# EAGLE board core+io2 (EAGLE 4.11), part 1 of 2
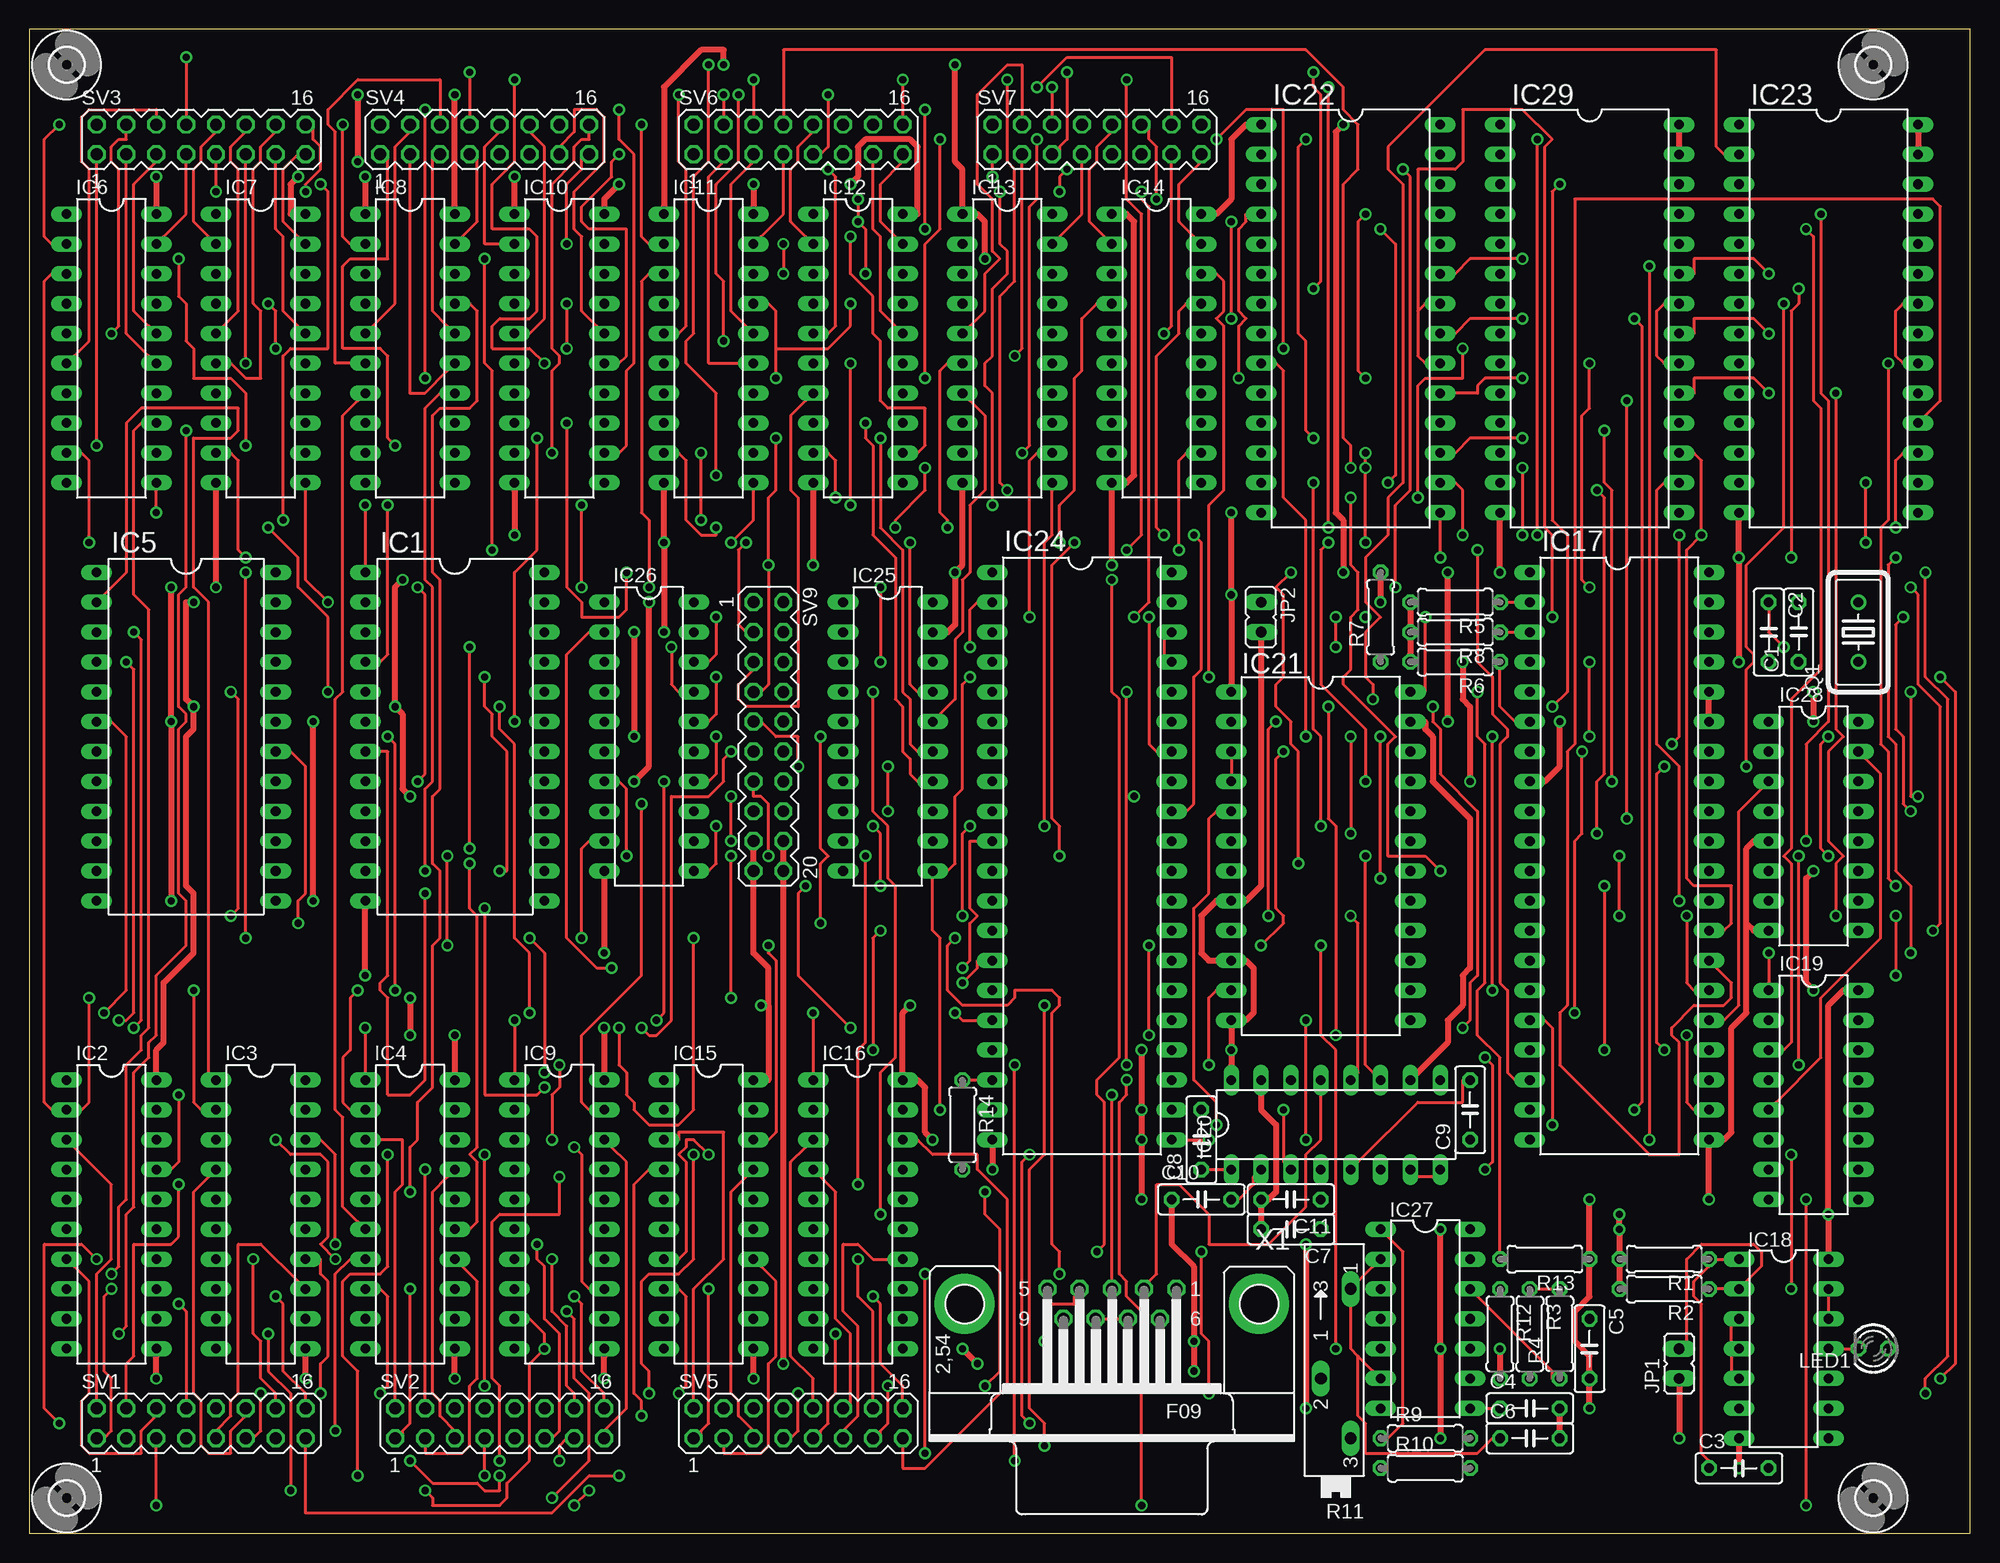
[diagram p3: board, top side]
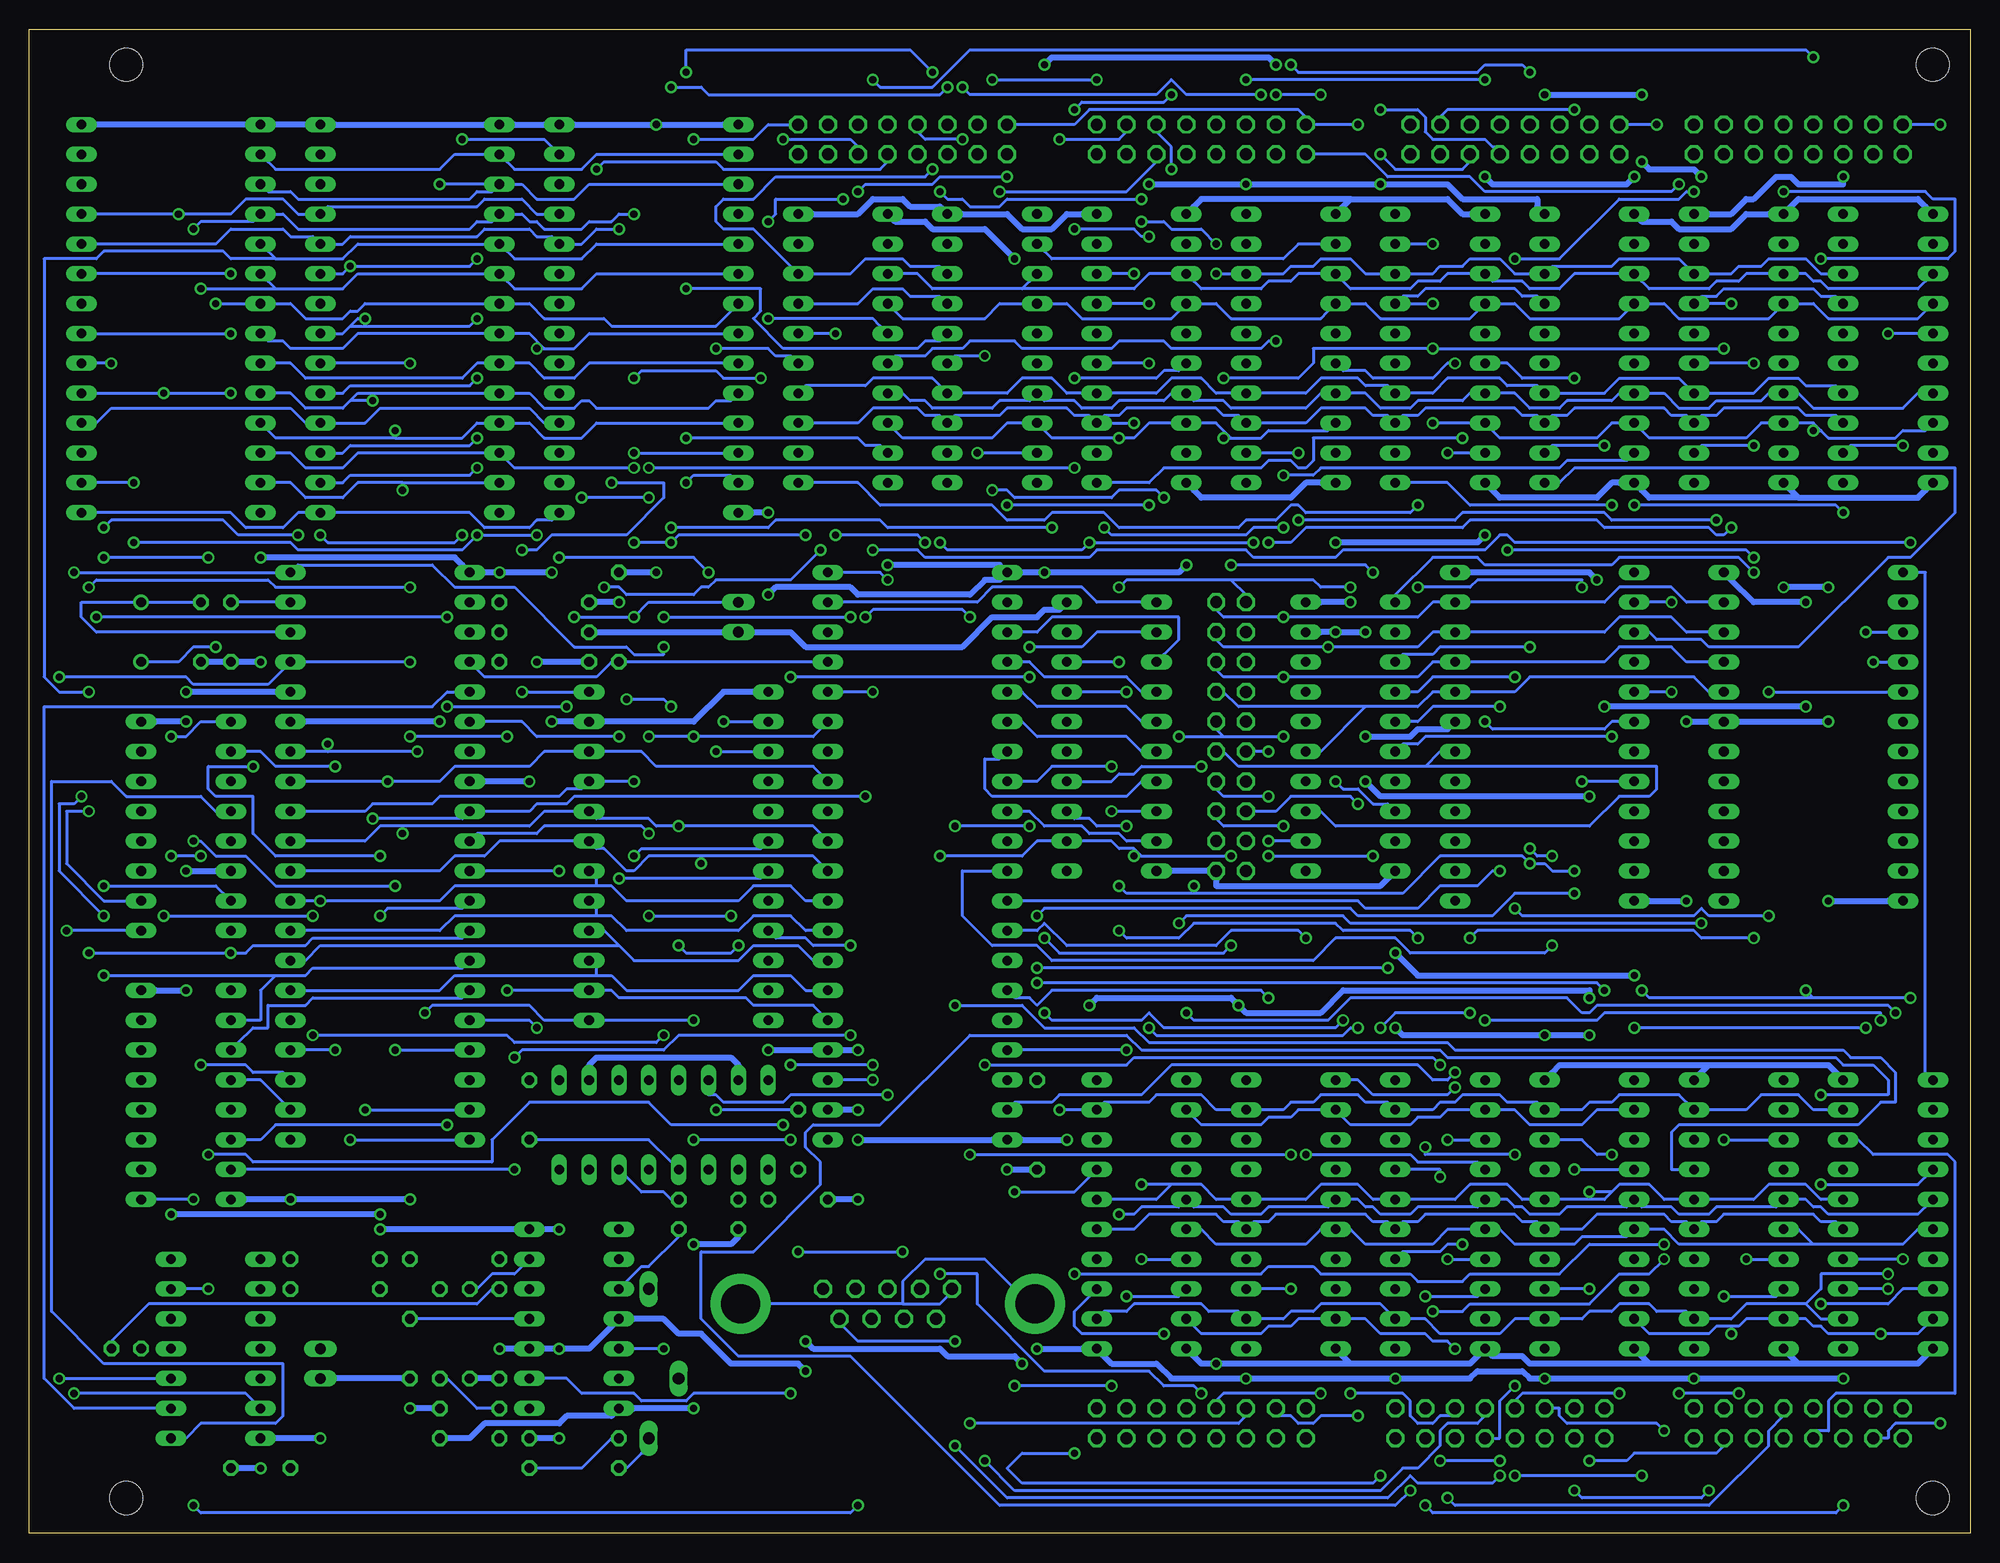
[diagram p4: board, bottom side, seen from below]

Size 165.08 x 127.94 mm. Coordinates in mm from the lower left corner, seen from the top.
Outline: 0,0 165.08,0 165.08,127.94 0,127.94 0,0
Copper layers (1*16): Top 0.035mm / dielectric 1.5mm / Bottom 0.035mm
Design rules "default": minimum track width 10mil, minimum drill 24mil, track to track 8mil, track to pad 8mil, pad to pad 8mil, via to via 8mil, smd to smd 8mil, copper to edge 40mil, drill to drill 8mil, minimum pad ring 10mil, minimum via ring 8mil, stop-mask expansion 4mil, vias tented up to drill 0mil, thermal gap 10mil
Net classes: 1 Power: width 0.508 mm, drill 0.254 mm, clearance 0.254 mm

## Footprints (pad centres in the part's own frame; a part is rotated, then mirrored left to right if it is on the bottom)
C050-025X075 = drill 0.813 octagon: 1 -2.54,0; 2 2.54,0
DIL24-6 = drill 0.813 long: 1 -13.97,-7.62; 2 -11.43,-7.62; 3 -8.89,-7.62; 4 -6.35,-7.62; 5 -3.81,-7.62; 6 -1.27,-7.62; 7 1.27,-7.62; 8 3.81,-7.62; 9 6.35,-7.62; 10 8.89,-7.62; 11 11.43,-7.62; 12 13.97,-7.62; 13 13.97,7.62; 14 11.43,7.62; 15 8.89,7.62; 16 6.35,7.62; 17 3.81,7.62; 18 1.27,7.62; 19 -1.27,7.62; 20 -3.81,7.62; 21 -6.35,7.62; 22 -8.89,7.62; 23 -11.43,7.62; 24 -13.97,7.62
DIL20 = drill 0.813 long: 1 -11.43,-3.81; 2 -8.89,-3.81; 3 -6.35,-3.81; 4 -3.81,-3.81; 5 -1.27,-3.81; 6 1.27,-3.81; 7 3.81,-3.81; 8 6.35,-3.81; 9 8.89,-3.81; 10 11.43,-3.81; 11 11.43,3.81; 12 8.89,3.81; 13 6.35,3.81; 14 3.81,3.81; 15 1.27,3.81; 16 -1.27,3.81; 17 -3.81,3.81; 18 -6.35,3.81; 19 -8.89,3.81; 20 -11.43,3.81
DIL40 = drill 0.813 long: 1 -24.13,-7.62; 2 -21.59,-7.62; 3 -19.05,-7.62; 4 -16.51,-7.62; 5 -13.97,-7.62; 6 -11.43,-7.62; 7 -8.89,-7.62; 8 -6.35,-7.62; 9 -3.81,-7.62; 10 -1.27,-7.62; 11 1.27,-7.62; 12 3.81,-7.62; 13 6.35,-7.62; 14 8.89,-7.62; 15 11.43,-7.62; 16 13.97,-7.62; 17 16.51,-7.62; 18 19.05,-7.62; 19 21.59,-7.62; 20 24.13,-7.62; 21 24.13,7.62; 22 21.59,7.62; 23 19.05,7.62; 24 16.51,7.62; 25 13.97,7.62; 26 11.43,7.62; 27 8.89,7.62; 28 6.35,7.62; 29 3.81,7.62; 30 1.27,7.62; 31 -1.27,7.62; 32 -3.81,7.62; 33 -6.35,7.62; 34 -8.89,7.62; 35 -11.43,7.62; 36 -13.97,7.62; 37 -16.51,7.62; 38 -19.05,7.62; 39 -21.59,7.62; 40 -24.13,7.62
DIL14 = drill 0.813 long: 1 -7.62,-3.81; 2 -5.08,-3.81; 3 -2.54,-3.81; 4 0,-3.81; 5 2.54,-3.81; 6 5.08,-3.81; 7 7.62,-3.81; 8 7.62,3.81; 9 5.08,3.81; 10 2.54,3.81; 11 0,3.81; 12 -2.54,3.81; 13 -5.08,3.81; 14 -7.62,3.81
DIL16 = drill 0.813 long: 1 -8.89,-3.81; 2 -6.35,-3.81; 3 -3.81,-3.81; 4 -1.27,-3.81; 5 1.27,-3.81; 6 3.81,-3.81; 7 6.35,-3.81; 8 8.89,-3.81; 9 8.89,3.81; 10 6.35,3.81; 11 3.81,3.81; 12 1.27,3.81; 13 -1.27,3.81; 14 -3.81,3.81; 15 -6.35,3.81; 16 -8.89,3.81
DIL24 = drill 0.813 long: 1 -13.97,-7.62; 2 -11.43,-7.62; 3 -8.89,-7.62; 4 -6.35,-7.62; 5 -3.81,-7.62; 6 -1.27,-7.62; 7 1.27,-7.62; 8 3.81,-7.62; 9 6.35,-7.62; 10 8.89,-7.62; 11 11.43,-7.62; 12 13.97,-7.62; 13 13.97,7.62; 14 11.43,7.62; 15 8.89,7.62; 16 6.35,7.62; 17 3.81,7.62; 18 1.27,7.62; 19 -1.27,7.62; 20 -3.81,7.62; 21 -6.35,7.62; 22 -8.89,7.62; 23 -11.43,7.62; 24 -13.97,7.62
DIL28 = drill 0.813 long: 1 -16.51,-7.62; 2 -13.97,-7.62; 3 -11.43,-7.62; 4 -8.89,-7.62; 5 -6.35,-7.62; 6 -3.81,-7.62; 7 -1.27,-7.62; 8 1.27,-7.62; 9 3.81,-7.62; 10 6.35,-7.62; 11 8.89,-7.62; 12 11.43,-7.62; 13 13.97,-7.62; 14 16.51,-7.62; 15 16.51,7.62; 16 13.97,7.62; 17 11.43,7.62; 18 8.89,7.62; 19 6.35,7.62; 20 3.81,7.62; 21 1.27,7.62; 22 -1.27,7.62; 23 -3.81,7.62; 24 -6.35,7.62; 25 -8.89,7.62; 26 -11.43,7.62; 27 -13.97,7.62; 28 -16.51,7.62
JP1 = drill 0.914 long: 1 0,-1.27; 2 0,1.27
LED3MM = drill 0.813 octagon: A -1.27,0; K 1.27,0
HC18U-V = drill 0.813 round: 1 -2.54,0; 2 2.54,0
0207/7 = drill 0.813 octagon: 1 -3.81,0; 2 3.81,0
SP19L = drill 1.016 long: A 5.715,-1.27; E -6.985,-1.27; S -1.905,1.27
MA08-2 = drill 1.016 octagon: 1 -8.89,-1.27; 2 -8.89,1.27; 3 -6.35,-1.27; 4 -6.35,1.27; 5 -3.81,-1.27; 6 -3.81,1.27; 7 -1.27,-1.27; 8 -1.27,1.27; 9 1.27,-1.27; 10 1.27,1.27; 11 3.81,-1.27; 12 3.81,1.27; 13 6.35,-1.27; 14 6.35,1.27; 15 8.89,-1.27; 16 8.89,1.27
MA10-2 = drill 1.016 octagon: 1 -11.43,-1.27; 2 -11.43,1.27; 3 -8.89,-1.27; 4 -8.89,1.27; 5 -6.35,-1.27; 6 -6.35,1.27; 7 -3.81,-1.27; 8 -3.81,1.27; 9 -1.27,-1.27; 10 -1.27,1.27; 11 1.27,-1.27; 12 1.27,1.27; 13 3.81,-1.27; 14 3.81,1.27; 15 6.35,-1.27; 16 6.35,1.27; 17 8.89,-1.27; 18 8.89,1.27; 19 11.43,-1.27; 20 11.43,1.27
2,8 = hole 2.8: 0,0
F09HP = drill 1.016 octagon: 1 -5.486,-1.27; 2 -2.743,-1.27; 3 0,-1.27; 4 2.743,-1.27; 5 5.486,-1.27; 6 -4.115,1.27; 7 -1.372,1.27; 8 1.372,1.27; 9 4.115,1.27 | drill 3.302 pad 5.08 round: G1 -12.522,0; G2 12.522,0

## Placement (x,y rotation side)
C1  27pf  [C050-025X075]  150.49,76.67 90 top
C2  27pf  [C050-025X075]  147.95,76.67 270 top
C3  22uf  [C050-025X075]  145.41,5.55 0 top
C4  0.1uf  [C050-025X075]  127.63,10.63 0 top
C5  10uf  [C050-025X075]  132.71,15.71 270 top
C6  330pf  [C050-025X075]  127.63,8.09 0 top
C7  10uf  [C050-025X075]  107.31,25.87 180 top
C8  0.1uf  [C050-025X075]  99.69,33.49 90 top
C9  0.1uf  [C050-025X075]  122.55,36.03 90 top
C10  0.1uf  [C050-025X075]  99.69,28.41 0 top
C11  0.1uf  [C050-025X075]  107.31,28.41 180 top
IC1  74154N  [DIL24-6]  36.19,67.78 270 top
IC2  74LS373N  [DIL20]  6.98,27.14 270 top
IC3  74LS373N  [DIL20]  19.68,27.14 270 top
IC4  74LS373N  [DIL20]  32.38,27.14 270 top
IC5  74154N  [DIL24-6]  13.33,67.78 270 top
IC6  74LS374N  [DIL20]  6.98,100.8 270 top
IC7  74LS374N  [DIL20]  19.68,100.8 270 top
IC8  74LS374N  [DIL20]  32.38,100.8 270 top
IC9  74LS373N  [DIL20]  45.08,27.14 270 top
IC10  74LS374N  [DIL20]  45.08,100.8 270 top
IC11  74LS374N  [DIL20]  57.78,100.8 270 top
IC12  74LS374N  [DIL20]  70.48,100.8 270 top
IC13  74LS374N  [DIL20]  83.18,100.8 270 top
IC14  74LS374N  [DIL20]  95.88,100.8 270 top
IC15  74LS373N  [DIL20]  57.78,27.14 270 top
IC16  74LS373N  [DIL20]  70.48,27.14 270 top
IC17  [DIL40]  135.25,57.62 270 top
IC18  74LS00N  [DIL14]  149.22,15.71 270 top
IC19  74LS138N  [DIL16]  151.76,37.3 270 top
IC20  MAX232  [DIL16]  111.12,34.76 0 top
IC21  [DIL24]  109.85,57.62 270 top
IC22  5565  [DIL28]  112.39,103.34 270 top
IC23  2764  [DIL28]  153.03,103.34 270 top
IC24  [DIL40]  89.53,57.62 270 top
IC25  74LS245N  [DIL20]  73.02,67.78 270 top
IC26  74LS245N  [DIL20]  52.7,67.78 270 top
IC27  LM556N  [DIL14]  118.74,18.25 270 top
IC28  74LS138N  [DIL16]  151.76,60.16 270 top
IC29  2764  [DIL28]  132.71,103.34 270 top
JP1  RESET  [JP1]  140.33,14.44 0 top
JP2  DEBUG  [JP1]  104.77,77.94 180 top
LED1  [LED3MM]  156.84,15.71 180 top
Q1  4Mhz  [HC18U-V]  155.57,76.67 90 top
R1  10K  [0207/7]  139.06,23.33 180 top
R2  10K  [0207/7]  139.06,20.79 180 top
R3  100K  [0207/7]  127.63,16.98 270 top
R4  100K  [0207/7]  130.17,16.98 90 top
R5  3.3K  [0207/7]  121.28,79.21 180 top
R6  3.3K  [0207/7]  121.28,74.13 180 top
R7  3.3K  [0207/7]  114.93,77.94 90 top
R8  3.3K  [0207/7]  121.28,76.67 180 top
R9  1.8K  [0207/7]  118.74,8.09 0 top
R10  10K  [0207/7]  118.74,5.55 0 top
R11  10K  [SP19L]  111.12,15.08 90 top
R12  270  [0207/7]  125.09,16.98 270 top
R13  1K  [0207/7]  128.9,23.33 180 top
R14  3.3K  [0207/7]  79.37,34.76 270 top
SV1  [MA08-2]  14.6,9.36 0 top
SV2  [MA08-2]  40,9.36 0 top
SV3  [MA08-2]  14.6,118.58 0 top
SV4  [MA08-2]  38.73,118.58 0 top
SV5  [MA08-2]  65.4,9.36 0 top
SV6  [MA08-2]  65.4,118.58 0 top
SV7  [MA08-2]  90.8,118.58 0 top
SV9  [MA10-2]  62.86,67.78 270 top
U$1  [2,8]  156.84,3.01 0 top
U$2  [2,8]  156.84,124.93 0 top
U$3  [2,8]  3.17,124.93 0 top
U$4  [2,8]  3.17,3.01 0 top
X1  [F09HP]  92.07,19.52 180 top

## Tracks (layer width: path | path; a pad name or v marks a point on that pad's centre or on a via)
A00  (via drill 0.61)
  Top 0.254: v93.34,39.84 93.34,62.7 | 93.34,62.7 v93.34,71.59 | v100.32,39.84 100.32,45.55 100.96,46.19 IC21.11 | v135.88,60.8 v135.88,96.36 | 93.34,62.7 v93.97,62.7
  Bottom 0.254: v93.34,71.59 95.88,71.59 IC24.36 | v93.34,39.84 v100.32,39.84 | 137.79,96.36 138.42,95.72 141.6,95.72 142.87,96.99 144.14,96.99 IC23.10 | 137.79,96.36 137.16,96.99 126.36,96.99 IC29.10 123.82,96.99 122.55,96.99 121.28,95.72 118.74,95.72 118.1,96.36 117.47,96.36 116.83,95.72 107.31,95.72 106.67,96.36 105.41,96.36 IC22.10 | v135.88,60.8 128.27,60.8 IC17.9 126.36,61.43 122.55,61.43 121.91,62.06 119.38,62.06 118.74,62.7 v93.97,62.7 | v135.88,96.36 137.79,96.36
A01  (via drill 0.61)
  Top 0.254: v112.39,67.78 v112.39,59.52 | v108.58,67.78 108.58,86.19 106.67,88.1 106.67,98.89 106.04,99.53 IC22.9
  Bottom 0.254: v112.39,67.78 v108.58,67.78 98.42,67.78 97.78,68.41 IC24.35 | v112.39,59.52 113.02,60.16 121.28,60.16 121.91,59.52 126.99,59.52 IC17.10 | IC23.9 144.14,99.53 142.87,99.53 141.6,98.26 128.27,98.26 126.99,99.53 126.36,99.53 IC29.9 123.82,99.53 122.55,99.53 121.28,98.26 118.74,98.26 117.47,99.53 106.04,99.53 IC22.9
A02  (via drill 0.61)
  Top 0.254: v120.01,56.35 118.74,57.62 115.56,57.62 115.56,67.14 116.2,67.78 111.75,72.22 111.75,72.86 112.39,73.5 112.39,77.94 113.02,78.58 113.02,81.75 112.39,82.39 v112.39,88.1 | v118.1,88.1 118.1,97.62 118.74,98.26 121.91,98.26 v121.91,100.8
  Bottom 0.254: 121.28,100.8 118.74,100.8 117.47,102.07 106.04,102.07 IC22.8 | 121.28,100.8 122.55,102.07 123.82,102.07 IC29.8 126.36,102.07 137.16,102.07 138.42,100.8 142.87,100.8 143.5,101.44 144.78,101.44 IC23.8 | v120.01,56.35 126.36,56.35 IC17.11 | v112.39,88.1 v118.1,88.1 | v121.91,100.8 121.28,100.8
A03  (via drill 0.61)
  Top 0.254: v135.25,52.54 v135.25,57.62 | v146.04,65.24 146.04,73.5 146.68,74.13 146.68,74.77 146.04,75.4 146.04,82.39 149.22,85.56 v149.22,104.61
  Bottom 0.254: IC22.7 105.41,103.97 106.67,102.7 115.56,102.7 116.2,103.34 121.28,103.34 122.55,104.61 123.82,104.61 IC29.7 126.36,104.61 136.52,104.61 137.16,103.97 137.79,103.97 138.42,103.34 141.6,103.34 142.87,104.61 144.14,104.61 IC23.7 146.68,104.61 v149.22,104.61 | v135.25,52.54 134.62,53.17 128.27,53.17 IC17.12 | v135.25,57.62 144.14,57.62 146.04,59.52 146.04,62.7 149.22,62.7 149.85,63.34 149.85,65.24 v146.04,65.24
A04  (via drill 0.61)
  Top 0.254: v147.95,49.37 147.95,46.82 IC19.1 | v160.01,49.37 160.01,55.08 158.75,56.35 158.75,67.14 158.11,67.78 158.11,82.39 v158.75,83.02 | v149.85,83.02 149.85,103.97 150.49,104.61 v150.49,105.88
  Bottom 0.254: IC17.13 128.27,50.63 140.97,50.63 141.6,50 146.04,50 146.68,49.37 v147.95,49.37 v160.01,49.37 | IC22.6 106.04,107.15 116.83,107.15 118.1,105.88 123.82,105.88 124.45,106.52 IC29.6 126.36,107.15 137.16,107.15 138.42,105.88 144.14,105.88 | 144.14,105.88 144.78,106.52 IC23.6 | v149.85,83.02 v158.75,83.02 | v150.49,105.88 144.14,105.88
A05  (via drill 0.61)
  Top 0.254: v158.75,52.54 v158.75,47.46 | v160.65,62.7 160.01,62.7 v160.01,71.59
  Bottom 0.254: 144.14,47.46 141.6,47.46 140.97,48.09 128.27,48.09 IC17.14 | 144.14,47.46 145.41,46.19 145.41,43.65 146.68,43.65 IC19.2 | IC22.5 106.04,109.69 116.83,109.69 118.1,108.42 123.82,108.42 124.45,109.05 IC29.5 126.36,109.69 137.16,109.69 138.42,108.42 144.14,108.42 | 144.14,108.42 144.78,109.05 IC23.5 | v158.75,47.46 144.14,47.46 | v158.75,52.54 162.56,56.35 162.56,62.06 161.28,62.06 v160.65,62.7 | v160.01,71.59 162.56,71.59 163.82,72.86 163.82,108.42 159.38,108.42 158.75,109.05 148.59,109.05 147.95,108.42 144.14,108.42
A06  (via drill 0.61)
  Top 0.254: v102.86,98.26 102.86,102.7 103.5,103.34 102.86,103.97 102.86,110.96 103.5,111.59 103.5,112.23 IC22.4 | v113.66,98.26 113.02,98.89 113.02,111.59 v113.66,112.23 | v151.12,110.96 151.76,110.33 151.76,96.36 152.39,95.72 152.39,73.5 149.85,70.95 149.85,58.25 149.22,57.62 149.85,56.98 149.85,41.74 149.22,41.11 IC19.3
  Bottom 0.254: IC19.3 147.31,41.74 146.04,43.02 144.78,43.02 144.78,44.92 141.6,44.92 140.97,45.55 128.27,45.55 IC17.15 | v102.86,98.26 106.04,98.26 106.67,98.89 113.02,98.89 v113.66,98.26 | v113.66,112.23 114.93,112.23 115.56,111.59 117.47,111.59 118.1,110.96 121.28,110.96 121.91,111.59 122.55,111.59 123.19,112.23 123.82,112.23 IC29.4 125.72,111.59 126.99,111.59 127.63,110.96 142.23,110.96 143.5,112.23 144.14,112.23 IC23.4 146.04,111.59 150.49,111.59 v151.12,110.96
A07  (via drill 0.61)
  Top 0.254: v129.53,34.76 129.53,43.02 128.9,43.65 IC17.16 | v121.91,43.02 122.55,43.65 122.55,46.82 123.19,47.46 123.19,61.43 120.01,64.61 120.01,68.41 119.38,69.05 v119.38,70.32 | v129.53,70.32 130.81,71.59 130.81,84.92 129.53,86.19 129.53,114.14 v130.17,114.77
  Bottom 0.254: v129.53,34.76 144.14,34.76 145.41,33.49 146.68,33.49 IC19.6 | IC22.3 106.04,114.77 117.47,114.77 118.74,113.5 121.91,113.5 123.19,114.77 123.82,114.77 IC29.3 | IC23.3 144.78,114.14 142.87,114.14 142.23,113.5 127.63,113.5 126.99,114.14 125.72,114.14 IC29.3 | v121.91,43.02 122.55,43.65 126.36,43.65 IC17.16 | v129.53,70.32 v119.38,70.32 | v130.17,114.77 126.36,114.77 IC29.3
A08  (via drill 0.61)
  Top 0.254: v133.98,55.08 v133.98,41.11 | v151.12,58.89 151.12,67.14 153.03,69.05 153.03,96.36 152.39,96.99 v152.39,112.23
  Bottom 0.254: IC22.25 121.28,112.23 121.91,112.23 123.19,113.5 126.36,113.5 126.99,112.86 139.69,112.86 IC29.25 141.6,112.23 142.23,112.23 143.5,113.5 146.68,113.5 147.95,112.23 v152.39,112.23 159.38,112.23 IC23.25 | v133.98,41.11 128.9,41.11 IC17.17 | v133.98,55.08 144.14,55.08 146.68,57.62 149.22,57.62 150.49,58.89 v151.12,58.89
A09  (via drill 0.61)
  Top 0.254: v123.19,83.66 123.19,74.13 124.45,72.86 124.45,69.69 125.72,68.41 125.72,67.78 125.09,67.14 125.09,46.82 125.72,46.19 125.72,39.2 126.36,38.57 IC17.18 | v115.56,89.37 116.2,90 116.2,109.69 v114.93,110.96
  Bottom 0.254: v123.19,83.66 121.91,83.66 120.64,84.92 114.3,84.92 111.12,88.1 111.12,89.37 v115.56,89.37 | v114.93,110.96 116.83,110.96 118.1,109.69 118.74,109.69 IC22.24 120.64,110.33 121.91,110.33 122.55,110.96 126.36,110.96 126.99,110.33 137.79,110.33 138.42,109.69 139.06,109.69 IC29.24 140.97,110.33 142.87,110.33 143.5,110.96 147.95,110.96 149.22,109.69 159.38,109.69 IC23.24
A10  (via drill 0.61)
  Top 0.254: v136.52,36.03 137.16,36.66 137.16,102.7 v136.52,103.34 | v126.99,103.34 122.55,103.34 121.28,102.07 IC22.21 | v147.95,102.07 146.68,103.34 141.6,103.34 141.6,102.07 IC29.21
  Bottom 0.254: v136.52,36.03 128.9,36.03 IC17.19 | v136.52,103.34 137.16,103.34 137.79,102.7 | 137.79,102.7 138.42,102.07 139.06,102.07 IC29.21 | v126.99,103.34 127.63,102.7 137.79,102.7 | v147.95,102.07 159.38,102.07 IC23.21
A11  (via drill 0.61)
  Top 0.254: v137.79,107.78 v137.79,33.49 | v126.99,108.42 122.55,108.42 121.28,107.15 IC22.23 | v147.95,107.15 146.68,108.42 141.6,108.42 141.6,107.15 IC29.23
  Bottom 0.254: v137.79,33.49 128.9,33.49 IC17.20 | IC29.23 139.06,107.15 138.42,107.15 v137.79,107.78 127.63,107.78 v126.99,108.42 | v147.95,107.15 159.38,107.15 IC23.23
A12  (via drill 0.61)
  Top 0.254: v140.97,42.38 140.97,36.66 141.6,36.03 IC17.22 | v111.12,42.38 111.12,60.16 110.48,60.8 v110.48,70.32 | v114.3,70.95 114.3,72.22 113.66,72.86 113.66,76.67 114.93,77.94 113.66,79.21 113.66,83.02 115.56,84.92 115.56,88.1 116.83,89.37 116.83,114.77 115.56,116.04 115.56,117.94 123.82,126.2 143.5,126.2 143.5,117.94 144.14,117.31 IC23.2
  Bottom 0.254: IC17.22 143.5,36.66 145.41,38.57 146.68,38.57 IC19.4 | IC22.2 106.04,117.31 116.83,117.31 118.1,116.04 123.82,116.04 124.45,116.67 IC29.2 126.36,117.31 128.9,117.31 130.17,116.04 144.14,116.04 144.78,116.67 IC23.2 | v140.97,42.38 124.45,42.38 123.82,41.74 111.75,41.74 v111.12,42.38 | v110.48,70.32 111.12,70.95 v114.3,70.95
A13  (via drill 0.61)
  Top 0.254: v150.49,39.84 v150.49,57.62 | v153.03,57.62 152.39,58.25 152.39,67.14 v153.03,67.78
  Bottom 0.254: v150.49,39.84 146.68,39.84 146.04,39.2 143.5,39.2 IC17.23 | v150.49,57.62 v153.03,57.62 | v153.03,67.78 151.76,67.78 150.49,69.05 149.22,69.05 IC28.1
A14  (via drill 0.61)
  Top 0.254: v139.06,41.11 138.42,41.74 138.42,64.61 v139.06,65.24
  Bottom 0.254: v139.06,41.11 141.6,41.11 IC17.24 | v139.06,65.24 144.14,65.24 145.41,66.51 146.68,66.51 IC28.2
A15
  Top 0.254: IC17.25 144.14,43.65 145.41,44.92 145.41,61.43 147.31,63.34 IC28.3
AB\  (via drill 0.61)
  Top 0.254: 118.1,103.97 118.74,104.61 IC22.22 | 118.1,103.97 118.1,100.16 118.74,99.53 IC22.20 | v160.01,61.43 159.38,62.06 159.38,67.78 158.75,68.41 158.75,77.3 v159.38,77.94 | v129.53,77.94 129.53,84.92 128.9,85.56 128.9,117.94 129.53,118.58 126.99,121.12 121.91,121.12 121.91,116.67 121.28,116.04 118.1,116.04 118.1,103.97
  Bottom 0.254: v160.01,61.43 161.92,61.43 161.92,56.98 158.75,53.81 156.84,53.81 IC28.10 | v129.53,77.94 v159.38,77.94
CB1
  Top 0.254: R14.1 80,38.57 80.64,38.57 IC24.18
CD\  (via drill 0.61)
  Top 0.254: IC29.22 139.06,104.61 138.42,103.97 138.42,100.16 139.06,99.53 IC29.20 | v161.92,51.27 162.56,51.91 162.56,70.32 160.65,72.22 160.65,79.84 v160.01,80.48 | v132.71,80.48 132.07,81.11 132.07,95.08 132.71,95.72 v132.71,99.53
  Bottom 0.254: v161.92,51.27 156.84,51.27 IC28.9 | v160.01,80.48 159.38,81.11 144.78,81.11 144.14,80.48 v132.71,80.48 | v132.71,99.53 139.06,99.53 IC29.20
D0  (via drill 0.61)
  Top 0.254: v133.98,93.81 133.98,89.37 134.62,88.73 v134.62,63.97
  Bottom 0.254: IC22.11 106.04,94.45 116.83,94.45 118.1,93.18 121.28,93.18 122.55,94.45 123.82,94.45 IC29.11 126.36,94.45 126.99,94.45 128.27,93.18 133.98,93.18 | 133.98,93.18 144.14,93.18 144.78,93.81 IC23.11 | IC24.33 97.78,64.61 98.42,65.24 111.75,65.24 113.02,66.51 116.2,66.51 IC21.22 118.74,66.51 121.28,66.51 122.55,65.24 128.9,65.24 130.17,63.97 v134.62,63.97 141.6,63.97 IC17.33 | v133.98,93.81 133.98,93.18
D1  (via drill 0.61)
  Top 0.254: v99.05,84.92 99.69,84.29 99.69,73.5 99.05,72.86 99.05,62.06 98.42,61.43 IC24.32 | v113.66,91.91 v113.66,90.64 v113.66,84.29 | v113.66,63.97 113.66,68.41 109.85,72.22 109.85,83.66 v110.48,84.29
  Bottom 0.254: IC17.32 141.6,61.43 136.52,61.43 135.88,62.06 130.81,62.06 130.17,62.7 120.01,62.7 119.38,63.34 118.1,63.34 IC21.21 116.2,63.97 v113.66,63.97 | IC23.12 144.14,91.91 142.87,91.91 141.6,90.64 138.42,90.64 137.16,91.91 126.36,91.91 IC29.12 124.45,91.28 123.82,90.64 v113.66,90.64 | v99.05,84.92 109.85,84.92 v110.48,84.29 v113.66,84.29 | v113.66,91.91 106.04,91.91 IC22.12
D2  (via drill 0.61)
  Top 0.254: v109.21,89.37 109.21,68.41 109.85,67.78 v109.85,60.16 | v133.34,88.73 133.98,88.1 133.98,64.61 133.34,63.97 v133.34,59.52
  Bottom 0.254: 133.34,89.37 137.16,89.37 138.42,88.1 141.6,88.1 142.87,89.37 144.14,89.37 IC23.13 | 133.34,89.37 126.36,89.37 IC29.13 | 133.34,60.16 135.25,60.16 136.52,58.89 141.6,58.89 IC17.31 | 133.34,60.16 122.55,60.16 121.28,61.43 118.74,61.43 IC21.20 116.83,60.8 112.39,60.8 111.75,60.16 v109.85,60.16 98.42,60.16 97.78,59.52 IC24.31 | v109.21,89.37 108.58,90 105.41,90 IC22.13 | v133.34,88.73 133.34,89.37 | 133.34,60.16 v133.34,59.52
D3  (via drill 0.61)
  Top 0.254: v120.01,83.02 120.01,86.19 IC22.15 | v107.31,81.75 106.04,80.48 106.67,79.84 106.67,72.86 106.04,72.22 106.04,70.32 107.31,69.05 107.31,67.14 107.94,66.51 v107.94,56.98
  Bottom 0.254: IC22.15 120.64,86.19 121.91,86.19 122.55,85.56 126.36,85.56 127.63,86.83 139.06,86.83 IC29.15 141.6,86.83 142.23,86.83 143.5,85.56 146.68,85.56 147.95,86.83 159.38,86.83 IC23.15 | 107.94,57.62 112.39,57.62 113.66,56.35 114.3,56.35 116.2,58.25 116.83,58.25 IC21.19 118.74,58.89 125.09,58.89 126.36,57.62 128.9,57.62 130.17,56.35 141.6,56.35 IC17.30 | 107.94,57.62 98.42,57.62 97.78,56.98 IC24.30 | v120.01,83.02 108.58,83.02 v107.31,81.75 | 107.94,57.62 v107.94,56.98
D4  (via drill 0.61)
  Top 0.254: v121.91,84.92 121.91,88.73 121.28,89.37 IC22.16 | v126.99,90.64 v126.99,84.92 | v156.2,84.29 v156.2,89.37 | v140.33,53.81 140.33,65.24 138.42,67.14 138.42,88.73 139.06,89.37 IC29.16
  Bottom 0.254: v121.91,84.92 v126.99,84.92 128.27,83.66 142.23,83.66 142.87,84.29 v156.2,84.29 | v126.99,90.64 127.63,90 137.79,90 138.42,89.37 139.06,89.37 IC29.16 | v156.2,89.37 159.38,89.37 IC23.16 | 116.83,55.08 115.56,55.08 114.3,53.81 104.77,53.81 103.5,55.08 100.32,55.08 99.05,53.81 98.42,53.81 IC24.29 | 116.83,55.08 128.9,55.08 130.17,53.81 v140.33,53.81 141.6,53.81 IC17.29 | 116.83,55.08 116.83,55.71 IC21.18
D5  (via drill 0.61)
  Top 0.254: v126.99,93.18 122.55,93.18 121.28,91.91 IC22.17 | v158.75,85.56 158.75,91.28 159.38,91.91 IC23.17 | IC29.17 141.6,91.91 142.23,91.28 v142.23,84.92 140.97,83.66 140.97,55.71 141.6,55.08 144.78,55.08 144.78,51.91 144.14,51.27 IC17.28
  Bottom 0.254: v126.99,93.18 127.63,92.55 137.79,92.55 138.42,91.91 139.06,91.91 IC29.17 | v158.75,85.56 158.11,86.19 148.59,86.19 147.31,84.92 v142.23,84.92 | 116.83,52.54 115.56,52.54 114.3,51.27 104.77,51.27 103.5,52.54 100.32,52.54 99.05,51.27 98.42,51.27 IC24.28 | 116.83,52.54 128.9,52.54 130.17,51.27 141.6,51.27 IC17.28 | 116.83,52.54 116.83,53.17 IC21.17
D6
  Top 0.254: IC23.18 161.28,95.08 162.56,96.36 162.56,112.86 161.92,113.5 131.44,113.5 131.44,67.14 130.81,66.51 130.81,44.92 130.17,44.28 130.17,39.84 137.79,32.22 140.33,32.22 140.33,41.74 139.69,42.38 139.69,43.02 141.6,44.92 144.14,44.92 144.78,45.55 144.78,46.82 143.5,48.09 IC17.27
  Bottom 0.254: IC22.18 121.28,94.45 122.55,95.72 135.25,95.72 136.52,94.45 139.06,94.45 IC29.18 141.6,94.45 142.87,95.72 158.11,95.72 159.38,94.45 IC23.18 | 114.93,50 116.2,51.27 IC21.16 | 114.93,50 113.66,48.73 104.77,48.73 103.5,50 99.69,50 98.42,48.73 IC24.27 | 114.93,50 140.33,50 141.6,48.73 IC17.27
D7  (via drill 0.61)
  Top 0.254: v126.99,98.26 123.82,98.26 123.19,97.62 123.19,96.99 121.28,96.99 IC22.19 | v147.95,96.99 146.68,98.26 141.6,98.26 141.6,96.99 IC29.19 | v153.66,96.99 153.66,68.41 154.3,67.78 153.03,66.51 153.03,58.89 154.3,57.62 153.66,56.98 v153.66,52.54 | v140.97,52.54 140.97,46.82 141.6,46.19 IC17.26
  Bottom 0.254: v126.99,98.26 127.63,97.62 137.79,97.62 138.42,96.99 139.06,96.99 IC29.19 | v147.95,96.99 v153.66,96.99 159.38,96.99 IC23.19 | 116.83,47.46 115.56,47.46 114.3,46.19 104.77,46.19 103.5,47.46 100.32,47.46 99.05,46.19 98.42,46.19 IC24.26 | 116.83,47.46 128.9,47.46 130.17,46.19 141.6,46.19 IC17.26 | 116.83,47.46 116.83,48.09 IC21.15 | v153.66,52.54 v140.97,52.54
E  (via drill 0.61)
  Top 0.254: v162.56,13.17 163.82,14.44 163.82,71.59 v162.56,72.86 | v124.45,46.19 v124.45,67.78 | v132.71,67.78 v132.71,74.13
  Bottom 0.254: IC24.25 97.78,44.28 98.42,44.92 103.5,44.92 104.13,45.55 114.93,45.55 115.56,46.19 116.2,46.19 IC21.14 118.74,46.19 v124.45,46.19 | v162.56,13.17 154.3,13.17 IC18.10 | v162.56,72.86 151.76,72.86 151.12,72.22 144.78,72.22 143.5,73.5 IC17.37 141.6,74.13 v132.71,74.13 | v124.45,67.78 v132.71,67.78
EF\  (via drill 0.61)
  Top 0.254: IC23.22 159.38,104.61 158.75,103.97 158.75,100.16 159.38,99.53 IC23.20 | v158.75,55.08 158.11,55.71 158.11,66.51 157.47,67.14 157.47,85.56 158.11,86.19 v158.11,99.53
  Bottom 0.254: v158.75,55.08 149.22,55.08 148.59,54.45 IC28.7 | v158.11,99.53 159.38,99.53 IC23.20
GND  (via drill 0.61)
  Top 0.508: v64.13,14.44 64.13,55.71 SV9.20 64.13,56.98 64.13,58.25 SV9.18 | 146.04,51.91 146.68,51.27 IC28.8 | 146.04,51.91 146.04,58.25 146.68,58.89 IC28.5 | v132.71,28.41 132.71,23.96 R13.1 132.71,22.7 132.71,20.15 131.44,18.88 131.44,16.34 132.71,15.08 132.71,13.81 C5.2 132.71,12.54 v132.71,10.63 | v142.87,28.41 142.87,32.85 IC17.21 144.14,33.49 144.78,34.12 144.78,43.02 146.04,44.28 146.04,51.91 | C7.2 104.77,26.5 104.77,27.77 C11.2 105.41,28.41 106.04,29.04 106.04,34.76 104.77,36.03 104.77,37.3 IC20.15 | C4.2 130.17,10 130.17,8.73 C6.2 | v145.41,5.55 145.41,7.46 IC18.7 | v140.33,8.09 140.33,12.54 JP1.1 | v108.58,24.6 v108.58,10.63 | v102.23,86.83 v102.23,79.84 102.23,72.22 IC21.1 | v125.09,81.75 125.09,86.19 IC29.14 | v145.41,74.13 v145.41,83.02 145.41,86.19 IC23.14 | v120.64,69.05 v120.64,81.75 | v28.57,115.41 28.57,112.86 IC8.1 | v41.27,115.41 41.27,112.86 IC10.1 | IC25.19 78.1,76.67 78.73,77.3 v78.73,81.75 79.37,82.39 79.37,88.73 IC13.10 | v81.27,108.42 81.27,111.59 80.64,112.23 IC13.1 79.37,112.86 79.37,116.04 78.73,116.67 v78.73,124.93 | v92.07,82.39 92.07,88.73 IC14.10 93.34,89.37 93.97,90 93.97,111.59 93.34,112.23 IC14.1 | v12.06,53.81 v12.06,69.05 v12.06,80.48 | v24.12,53.81 v24.12,69.05 | v51.43,76.67 v51.43,67.78 | v53.97,76.67 v53.97,84.29 53.97,88.73 IC11.10 | v41.27,84.92 41.27,88.73 IC10.10 | v15.87,80.48 15.87,88.73 IC7.10 | v66.67,82.39 66.67,88.73 IC12.10 | v59.05,124.93 59.05,126.2 57.15,126.2 53.97,123.03 53.97,112.86 IC11.1 | IC20.10 118.1,39.2 120.64,41.74 120.64,43.65 121.91,44.92 121.91,47.46 122.55,48.09 122.55,60.8 119.38,63.97 119.38,67.78 118.74,68.41 118.74,69.05 IC21.23
  Top 0.508: v48.89,49.37 48.89,55.71 IC26.10 | v28.57,47.46 28.57,53.17 IC1.12
  Bottom 0.508: IC26.10 49.53,55.71 50.16,55.08 64.13,55.08 64.13,55.71 SV9.20 64.77,56.35 67.94,56.35 IC25.10 | 14.6,14.44 4.44,14.44 3.8,15.08 IC2.10 | 14.6,14.44 15.24,15.08 IC3.10 | 27.3,14.44 27.93,15.08 IC4.10 | 14.6,14.44 27.3,14.44 | 27.3,14.44 37.46,14.44 38.1,15.08 40.64,15.08 IC9.10 41.91,15.08 42.54,14.44 52.7,14.44 | 52.7,14.44 53.34,15.08 IC15.10 | 52.7,14.44 v64.13,14.44 65.4,14.44 66.03,15.08 IC16.10 | v132.71,28.41 v142.87,28.41 146.68,28.41 IC19.8 | IC20.15 104.77,39.84 105.41,40.48 116.83,40.48 117.47,39.84 IC20.10 | C6.2 129.53,8.09 127.63,8.09 126.36,9.36 120.01,9.36 119.38,10 115.56,10 IC27.7 113.66,10.63 v108.58,10.63 | v145.41,5.55 147.31,5.55 C3.2 | 139.06,13.17 133.34,13.17 C5.2 | 139.06,13.17 139.69,13.17 | v140.33,8.09 144.14,8.09 IC18.7 | v132.71,10.63 130.81,10.63 C4.2 | v108.58,24.6 105.41,24.6 104.77,25.23 C7.2 | v102.23,86.83 103.5,86.83 IC22.14 | IC21.1 103.5,71.59 106.04,71.59 108.58,69.05 116.2,69.05 IC21.23 118.74,69.05 v120.64,69.05 | C1.1 149.85,74.13 148.59,74.13 C2.2 147.31,74.13 v145.41,74.13 | v145.41,83.02 128.9,83.02 128.27,82.39 IC17.1 126.36,81.75 v125.09,81.75 v120.64,81.75 | IC6.1 3.8,112.86 4.44,113.5 14.6,113.5 15.24,112.86 IC7.1 17.14,112.23 19.04,112.23 20.31,110.96 24.76,110.96 25.39,111.59 27.93,111.59 IC8.1 | 52.7,113.5 44.45,113.5 43.18,112.23 42.54,112.23 IC10.1 | 52.7,113.5 53.34,112.86 IC11.1 | 52.7,113.5 65.4,113.5 66.03,112.86 IC12.1 | v28.57,115.41 29.2,114.77 40.64,114.77 v41.27,115.41 | v81.27,108.42 83.81,110.96 88.26,110.96 88.89,111.59 91.44,111.59 IC14.1 | v92.07,82.39 82.55,82.39 IC24.1 | IC24.1 80.64,81.75 v78.73,81.75 67.3,81.75 v66.67,82.39
  Bottom 0.508: v12.06,53.81 6.98,53.81 IC5.12 | v12.06,69.05 19.68,69.05 IC5.19 22.22,69.05 v24.12,69.05 | v24.12,53.81 27.3,53.81 IC1.12 | 14.6,88.1 4.44,88.1 3.8,88.73 IC6.10 | 14.6,88.1 15.24,88.73 IC7.10 | 14.6,88.1 27.3,88.1 27.93,88.73 IC8.10 29.84,89.37 30.47,89.37 31.74,88.1 40,88.1 40.64,88.73 IC10.10 | v51.43,67.78 47.62,67.78 46.98,68.41 44.45,68.41 IC1.19 | v51.43,76.67 v53.97,76.67 55.24,76.67 IC26.19 | IC12.10 66.03,88.73 65.4,88.1 57.78,88.1 56.51,89.37 55.24,89.37 IC11.10 | v41.27,84.92 41.91,84.29 v53.97,84.29 | v12.06,80.48 v15.87,80.48 | v59.05,124.93 59.69,125.56 78.1,125.56 v78.73,124.93 | v102.23,79.84 101.59,80.48 95.24,80.48 94.61,79.84 85.08,79.84 83.81,81.11 82.55,81.11 IC24.1 | v48.89,49.37 46.98,47.46 v28.57,47.46 | 139.06,13.17 JP1.1
HLT\
  Top 0.254: R5.1 125.72,79.21 126.36,79.21 IC17.2
IN00
  Bottom 0.254: IC2.1 3.8,39.2 3.8,81.75 4.44,81.75 IC5.1
IN01
  Top 0.254: IC5.2 6.34,79.84 8.25,81.75 8.25,94.45 9.52,95.72 17.77,95.72 17.77,93.81 17.14,93.18 13.97,93.18 13.97,80.48 15.24,79.21 15.24,39.2 IC3.1
IN02  (via drill 0.61)
  Top 0.254: v28.57,43.02 28.57,39.2 IC4.1 | v8.89,43.02 9.52,43.65 9.52,76.03 v8.89,76.67
  Bottom 0.254: v8.89,43.02 v28.57,43.02 | v8.89,76.67 6.98,76.67 IC5.3
IN03  (via drill 0.61)
  Top 0.254: v8.25,74.13 8.89,73.5 8.89,44.28 8.25,43.65 v7.62,43.65 | v41.27,43.65 41.27,39.2 IC9.1
  Bottom 0.254: v8.25,74.13 6.98,74.13 IC5.4 | v7.62,43.65 7.62,44.28 31.11,44.28 31.74,43.65 v41.27,43.65
IN04  (via drill 0.61)
  Top 0.254: v43.81,37.94 43.18,37.3 38.73,37.3 v38.73,53.17 | v17.14,52.54 17.77,53.17 17.77,70.95 v17.14,71.59
  Bottom 0.254: v43.81,37.94 44.45,37.3 50.8,37.3 52.07,38.57 52.7,38.57 IC15.1 | v38.73,53.17 38.1,52.54 23.49,52.54 22.86,53.17 22.22,52.54 v17.14,52.54 | v17.14,71.59 6.98,71.59 IC5.5
IN05  (via drill 0.61)
  Top 0.254: v6.34,44.28 8.25,46.19 8.25,67.78 6.98,69.05 IC5.6 | v66.67,44.28 66.67,39.2 IC16.1
  Bottom 0.254: v6.34,44.28 6.98,44.92 31.74,44.92 32.38,44.28 33.02,44.28 34.29,45.55 52.7,45.55 54.61,43.65 66.03,43.65 v66.67,44.28
IO-E\  (via drill 0.61)
  Top 0.254: v93.34,38.57 93.34,37.3 92.7,36.66 92.7,22.06 93.34,21.42 93.34,20.15 94.61,18.88 v94.61,2.38 | v151.12,2.38 v151.12,28.41
  Bottom 0.254: v93.34,38.57 95.88,38.57 IC24.23 | v94.61,2.38 95.24,1.74 150.49,1.74 v151.12,2.38 | v151.12,28.41 154.3,28.41 IC19.9
IO-F\  (via drill 0.61)
  Top 0.254: v95.24,42.38 v95.24,50 | v123.82,40.48 124.45,39.84 124.45,31.58 v123.82,30.95
  Bottom 0.254: v95.24,50 98.42,50 99.05,50.63 101.59,50.63 IC21.9 | v95.24,42.38 109.85,42.38 111.12,41.11 123.19,41.11 v123.82,40.48 | v123.82,30.95 146.68,30.95 IC19.7
IRQ\
  Top 0.254: IC24.37 96.52,74.77 96.52,76.03 IC24.38
  Bottom 0.254: IC24.37 98.42,74.13 114.3,74.13 R7.1 115.56,74.13 116.83,72.86 126.36,72.86 126.99,73.5 IC17.4
MR
  Top 0.254: R8.1 125.72,76.67 126.36,76.67 IC17.3
N$1  (via drill 0.61)
  Top 0.254: v20.95,33.49 22.22,32.22 24.76,32.22 25.39,31.58 25.39,25.23 24.76,24.6 v26.03,23.33 | v45.72,18.88 46.35,18.25 46.35,13.17 47.62,11.9 47.62,6.18 v44.45,3.01
  Bottom 0.254: v20.95,33.49 17.14,33.49 IC3.3 | v26.03,23.33 27.3,22.06 29.84,22.06 32.38,19.52 42.54,19.52 43.18,18.88 v45.72,18.88 | v44.45,3.01 43.81,2.38 22.22,2.38 17.14,7.46 17.14,8.73 15.87,10 SV1.10
N$2
  Top 0.254: IC3.4 15.24,30.31 13.97,29.04 13.97,11.9 14.6,11.27 14.6,7.46 15.24,6.82 17.14,6.82 17.14,8.73 18.41,10 SV1.12
N$3  (via drill 0.61)
  Top 0.254: v149.22,75.4 147.95,76.67 147.95,78.58 C2.1
  Bottom 0.254: C2.1 147.31,79.21 144.14,79.21 IC17.39 | v149.22,75.4 151.12,75.4 152.39,74.13 154.94,74.13 Q1.1
N$4
  Bottom 0.254: IC17.38 144.14,76.67 159.38,76.67 160.65,77.94 160.65,79.21 156.2,79.21 Q1.2 154.94,79.21 151.12,79.21 C1.2
N$5  (via drill 0.61)
  Top 0.254: v80,75.4 80,78.58 80.64,79.21 IC24.2
  Bottom 0.254: v80,75.4 75.56,75.4 74.29,76.67 70.48,76.67 IC25.2
N$6
  Top 0.254: IC18.5 144.78,13.81 144.78,15.08 IC18.4 144.78,16.34 144.78,17.61 IC18.3
N$7  (via drill 0.61)
  Top 0.254: v19.04,23.33 19.04,16.98 19.68,16.34 19.68,13.17 20.95,11.9 20.95,11.27 SV1.14
  Bottom 0.254: v19.04,23.33 17.14,23.33 IC3.7
N$8  (via drill 0.61)
  Top 0.254: v20.95,20.15 21.58,19.52 21.58,13.81 23.49,11.9 23.49,11.27 SV1.16
  Bottom 0.254: v20.95,20.15 16.5,20.15 IC3.8
N$9  (via drill 0.61)
  Top 0.254: v12.7,19.52 13.33,18.88 13.33,11.27 SV1.8
  Bottom 0.254: v12.7,19.52 6.98,19.52 5.71,20.79 4.44,20.79 IC2.8
N$10
  Top 0.254: IC2.7 3.8,22.7 5.08,21.42 5.08,11.9 4.44,11.27 4.44,7.46 5.08,6.82 9.52,6.82 9.52,8.73 10.79,10 SV1.6
N$11  (via drill 0.61)
  Top 0.254: v12.7,29.68 12.7,25.23 12.06,24.6 8.89,24.6 8.89,15.08 8.25,14.44 8.25,11.27 SV1.4
  Bottom 0.254: v12.7,29.68 4.44,29.68 3.8,30.31 IC2.4
N$12
  Top 0.254: IC2.3 3.8,32.85 6.98,29.68 6.98,23.33 5.71,22.06 5.71,11.27 SV1.2
N$13  (via drill 0.61)
  Top 0.254: v6.98,20.79 6.34,20.15 6.34,13.81 6.98,13.17 6.98,8.73 6.34,8.09 SV1.1
  Bottom 0.254: v6.98,20.79 9.52,20.79 IC2.13
N$14  (via drill 0.61)
  Top 0.254: v5.71,23.33 4.44,24.6 1.27,24.6 1.27,10.63 v2.54,9.36
  Bottom 0.254: v5.71,23.33 9.52,23.33 IC2.14 | v2.54,9.36 6.34,9.36 6.98,8.73 6.98,8.09 7.62,8.09 SV1.3
N$15  (via drill 0.61)
  Top 0.254: v10.79,2.38 10.79,7.46 SV1.5 | v46.35,2.38 v47.62,3.64 | v12.7,37.3 12.7,31.58 12.06,30.95 IC2.17
  Bottom 0.254: v10.79,2.38 11.43,1.74 45.72,1.74 v46.35,2.38 | v47.62,3.64 48.89,2.38 82.55,2.38 95.24,15.08 104.77,15.08 107.94,18.25 107.94,23.96 103.5,23.96 97.78,29.68 97.78,31.58 99.05,32.85 99.05,34.12 98.42,34.76 92.7,34.76 85.08,42.38 71.75,42.38 70.48,41.11 45.08,41.11 44.45,40.48 11.43,40.48 10.79,39.84 8.25,39.84 6.98,38.57 6.98,37.3 v12.7,37.3
N$16
  Bottom 0.254: IC2.18 9.52,33.49 8.25,32.22 1.9,32.22 1.27,31.58 1.27,11.9 11.43,11.9 12.06,11.27 12.06,8.73 13.33,8.73 SV1.7
N$17
  Top 0.254: IC3.13 22.86,21.42 19.68,24.6 17.77,24.6 17.77,11.9 17.14,11.27 17.14,10 15.87,8.73 SV1.9
N$18  (via drill 0.61)
  Top 0.254: v19.68,11.9 19.68,8.73 19.04,8.09 SV1.11 | v24.76,11.9 24.76,14.44 25.39,15.08 25.39,21.42 24.76,22.06 24.76,23.33 IC3.14
  Bottom 0.254: v19.68,11.9 v24.76,11.9
N$19  (via drill 0.61)
  Top 0.254: v32.38,6.18 34.29,4.28 38.1,4.28 38.73,3.64 40,3.64 v40,4.92 | v86.35,7.46 86.35,9.36 85.08,10.63 85.08,30.95 86.35,32.22 v86.35,44.92
  Bottom 0.254: v32.38,6.18 29.2,6.18 28.57,6.82 21.58,6.82 20.95,7.46 SV1.13 | v40,4.92 40.64,4.28 46.98,4.28 47.62,4.92 49.53,3.01 81.91,3.01 v86.35,7.46 | v86.35,44.92 80.64,44.92 78.73,43.02 71.11,43.02 69.84,41.74 44.45,41.74 43.81,41.11 10.79,41.11 10.16,40.48 7.62,40.48 6.34,39.2 6.34,36.66 7.62,36.66 9.52,34.76 24.76,34.76 25.39,34.12 25.39,30.95 24.76,30.95 IC3.17
N$20  (via drill 0.61)
  Top 0.254: v26.03,24.6 26.03,32.22 24.76,33.49 IC3.18 | v76.19,6.82 v76.19,22.06 | v50.16,4.92 47.62,4.92 44.45,1.74 23.49,1.74 23.49,7.46 SV1.15
  Bottom 0.254: v26.03,24.6 32.38,24.6 34.92,22.06 42.54,22.06 43.18,21.42 46.98,21.42 47.62,22.06 55.24,22.06 55.88,22.7 59.69,22.7 60.32,22.06 v76.19,22.06 | v76.19,6.82 80.64,6.82 81.91,5.55 80.64,4.28 50.8,4.28 v50.16,4.92
N$21
  Top 0.254: 142.87,6.18 C3.1 142.87,6.18 | IC18.1 144.14,23.33 143.5,23.33 R1.1 142.87,22.7 141.6,21.42 141.6,20.15 142.23,19.52 142.23,8.09 142.23,6.82 142.87,6.18
N$22
  Top 0.254: R2.1 143.5,20.79 144.14,20.79 IC18.2 146.04,21.42 147.31,22.7 147.31,23.96 146.68,24.6 142.23,24.6 140.97,23.33 140.97,16.34 JP1.2
N$23  (via drill 0.61)
  Top 0.254: IC21.3 102.23,65.88 102.23,64.61 IC21.4 | v111.12,15.71 111.12,41.11 109.85,42.38 v109.85,50 | v104.77,50 106.67,51.91 106.67,52.54 106.04,53.17 106.04,65.88 v106.67,66.51
  Bottom 0.254: v111.12,15.71 113.66,15.71 IC27.5 | v109.85,50 109.21,49.37 105.41,49.37 v104.77,50 | v106.67,66.51 103.5,66.51 IC21.3
N$24  (via drill 0.61)
  Top 0.254: v49.53,48.09 48.26,48.09 45.72,50.63 45.72,74.77 47.62,76.67 IC26.2 | v79.37,48.09 80,48.73 80,51.91 80.64,52.54 80,53.17 80,58.89 80.64,58.89 IC24.10
  Bottom 0.254: v49.53,48.09 v79.37,48.09
N$25  (via drill 0.61)
  Top 0.254: v37.46,58.25 v37.46,75.4 | v35.55,50 v35.55,57.62
  Bottom 0.254: v37.46,75.4 45.08,75.4 45.72,74.77 48.26,74.77 IC26.3 | v37.46,58.25 36.83,57.62 v35.55,57.62 | v35.55,50 36.19,49.37 47.62,49.37 48.89,50.63 53.97,50.63 55.88,48.73 78.1,48.73 79.37,50 83.18,50 85.72,52.54 85.72,56.35 83.18,56.35 IC24.11
N$26  (via drill 0.61)
  Top 0.254: v52.07,119.85 52.07,110.33 52.7,109.69 IC11.2
  Bottom 0.254: IC13.2 78.73,109.05 78.1,108.42 58.41,108.42 57.15,109.69 55.24,109.69 IC11.2 | SV7.2 81.27,119.85 76.19,119.85 74.92,121.12 57.15,121.12 56.51,120.48 SV6.2 55.88,119.85 v52.07,119.85
N$27
  Top 0.254: 113.02,15.08 112.39,15.71 112.39,19.52 R11.A 113.02,21.42 114.3,22.7 IC27.2 | 113.02,15.08 114.3,13.81 IC27.6 | 113.02,15.08 113.02,10 113.66,9.36 113.66,6.82 123.19,6.82 124.45,8.09 C6.1
N$28
  Top 0.254: IC27.1 115.56,25.23 116.83,23.96 116.83,9.36 115.56,8.09 R9.1
  Bottom 0.254: R9.1 115.56,8.09 118.1,5.55 121.91,5.55 R10.2
N$29  (via drill 0.61)
  Top 0.254: v44.45,33.49 44.45,37.3 45.08,37.94 v45.08,39.84 | v83.81,6.18 v83.81,39.84
  Bottom 0.254: v44.45,33.49 42.54,33.49 IC9.3 | v45.08,39.84 45.72,40.48 71.11,40.48 71.75,39.84 v83.81,39.84 | v83.81,6.18 81.27,3.64 50.16,3.64 48.26,5.55 46.98,5.55 45.08,7.46 45.08,8.73 44.45,9.36 41.91,9.36 41.27,10 SV2.10
N$30  (via drill 0.61)
  Top 0.254: v56.51,32.22 56.51,23.33 55.24,22.06 52.7,22.06 52.07,21.42 52.07,14.44 52.7,13.81 v52.7,11.9
  Bottom 0.254: v56.51,32.22 47.62,32.22 46.98,31.58 41.91,31.58 IC9.4 | v52.7,11.9 48.26,11.9 47.62,11.27 47.62,10 46.98,9.36 45.72,9.36 45.08,10 43.81,10 SV2.12
N$31  (via drill 0.61)
  Top 0.254: v44.45,23.33 44.45,18.88 45.72,17.61 45.72,12.54 46.35,11.9 46.35,11.27 SV2.14
  Bottom 0.254: v44.45,23.33 42.54,23.33 IC9.7
N$32  (via drill 0.61)
  Top 0.254: v46.35,20.15 46.98,19.52 46.98,13.81 48.89,11.9 48.89,11.27 SV2.16
  Bottom 0.254: v46.35,20.15 41.91,20.15 IC9.8
N$33  (via drill 0.61)
  Top 0.254: v31.11,92.55 30.47,93.18 30.47,100.16 29.84,100.8 26.66,100.8 26.66,107.78 27.3,108.42 30.47,108.42 30.47,117.31 SV4.1
  Bottom 0.254: v31.11,92.55 35.55,92.55 IC8.12
N$34
  Top 0.254: IC8.15 35.55,98.89 33.65,96.99 32.38,96.99 32.38,116.67 SV4.3
N$35
  Top 0.254: IC8.16 35.55,102.7 34.29,103.97 34.29,117.31 SV4.5
N$36
  Top 0.254: IC8.19 36.83,110.33 38.1,111.59 38.1,117.31 SV4.7
N$37
  Top 0.254: IC4.3 29.84,33.49 31.74,33.49 31.74,29.68 31.11,29.04 31.11,11.27 SV2.2
N$38  (via drill 0.61)
  Top 0.254: v33.65,30.95 33.65,11.27 SV2.4
  Bottom 0.254: v33.65,30.95 29.84,30.95 IC4.4
N$39  (via drill 0.61)
  Top 0.254: v26.03,8.73 26.03,22.06 27.3,23.33 IC4.7
  Bottom 0.254: v26.03,8.73 26.66,9.36 34.29,9.36 34.92,10 34.92,10.63 35.55,10.63 SV2.6
N$40  (via drill 0.61)
  Top 0.254: v29.84,11.9 30.47,12.54 30.47,20.15 29.84,20.79 IC4.8
  Bottom 0.254: v29.84,11.9 38.1,11.9 38.73,11.27 SV2.8
N$41  (via drill 0.61)
  Top 0.254: v46.35,32.85 46.98,32.22 46.98,21.42 47.62,20.79 IC9.13 | v38.73,12.54 v38.73,32.22
  Bottom 0.254: v46.35,32.85 46.35,32.22 v38.73,32.22 | v38.73,12.54 40,11.27 40,8.09 40.64,8.09 SV2.9
N$42  (via drill 0.61)
  Top 0.254: v43.18,24.6 43.18,23.33 43.81,22.7 43.81,18.25 45.08,16.98 45.08,8.73 44.45,8.09 SV2.11
  Bottom 0.254: v43.18,24.6 44.45,24.6 45.08,23.96 48.26,23.96 IC9.14
N$43  (via drill 0.61)
  Top 0.254: v45.08,6.18 45.08,7.46 45.72,8.09 SV2.13 | v40,6.18 40,12.54 39.37,13.17 39.37,26.5 40,27.14 45.08,27.14 v45.08,30.31
  Bottom 0.254: v40,6.18 v45.08,6.18 | v45.08,30.31 45.08,30.95 47.62,30.95 IC9.17
N$44
  Top 0.254: IC9.18 49.53,32.85 50.8,31.58 50.8,10.63 48.89,8.73 SV2.15
N$45  (via drill 0.61)
  Top 0.254: v32.38,20.79 32.38,9.36 31.74,8.73 31.74,8.09 SV2.1
  Bottom 0.254: v32.38,20.79 34.92,20.79 IC4.13
N$46
  Top 0.254: IC4.14 36.83,22.7 38.1,21.42 38.1,13.17 37.46,12.54 37.46,7.46 36.83,6.82 33.65,6.82 33.65,7.46 SV2.3
N$47
  Top 0.254: IC4.17 35.55,30.31 34.29,29.04 34.29,11.9 34.92,11.27 34.92,10 36.19,8.73 SV2.5
N$48  (via drill 0.61)
  Top 0.254: v38.73,4.92 38.73,7.46 SV2.7 | v27.93,4.92 27.93,13.81 26.66,15.08 26.66,21.42 27.3,22.06 29.84,22.06 30.47,22.7 v30.47,32.22
  Bottom 0.254: v27.93,4.92 v38.73,4.92 | v30.47,32.22 31.74,32.22 33.02,33.49 34.92,33.49 IC4.18
N$49
  Top 0.254: IC8.5 29.2,102.7 31.11,104.61 31.11,117.94 32.38,119.22 SV4.4
N$50
  Top 0.254: IC8.6 27.3,99.53 26.03,99.53 26.03,119.22 25.39,119.85 25.39,121.12 27.93,123.66 34.92,123.66 34.92,120.48 SV4.6
N$51  (via drill 0.61)
  Top 0.254: v26.66,119.85 26.66,110.33 27.3,109.69 IC8.2
  Bottom 0.254: v26.66,119.85 29.2,119.85 SV4.2
N$52  (via drill 0.61)
  Top 0.254: v58.41,90 58.41,96.99 55.88,99.53 55.88,101.44 56.51,102.07 56.51,115.41 57.78,116.67 v57.78,124.93 | v37.46,124.3 37.46,120.48 SV4.8
  Bottom 0.254: v58.41,90 55.88,90 55.24,90.64 34.92,90.64 34.29,91.28 29.2,91.28 IC8.9 | v57.78,124.93 57.15,124.3 41.91,124.3 41.27,124.93 38.1,124.93 v37.46,124.3
N$53  (via drill 0.61)
  Top 0.254: v5.71,92.55 5.71,116.67 SV3.1
  Bottom 0.254: v5.71,92.55 10.16,92.55 IC6.12
N$54
  Top 0.254: IC6.15 10.16,100.16 8.25,102.07 8.25,116.67 SV3.3
N$55
  Top 0.254: IC6.16 10.16,102.7 8.89,103.97 8.89,114.77 10.79,116.67 SV3.5
N$56
  Top 0.254: IC6.19 11.43,110.33 13.33,112.23 13.33,116.67 SV3.7
N$57  (via drill 0.61)
  Top 0.254: v2.54,119.85 1.27,118.58 1.27,110.33 1.9,109.69 IC6.2
  Bottom 0.254: v2.54,119.85 5.08,119.85 SV3.2
N$58  (via drill 0.61)
  Top 0.254: v6.98,102.07 7.62,102.7 7.62,116.04 6.98,116.67 6.98,117.94 7.62,118.58 8.25,118.58 8.25,119.22 SV3.4
  Bottom 0.254: v6.98,102.07 4.44,102.07 IC6.5
N$59
  Top 0.254: IC6.6 3.8,100.16 5.08,101.44 5.08,116.04 4.44,116.67 4.44,120.48 5.08,121.12 10.79,121.12 10.79,120.48 SV3.6
N$60  (via drill 0.61)
  Top 0.254: v5.08,84.29 5.08,91.28 4.44,91.91 IC6.9 | v93.34,83.66 94.61,84.92 94.61,112.23 93.34,113.5 v93.34,123.66 | v13.33,125.56 13.33,120.48 SV3.8
  Bottom 0.254: v5.08,84.29 38.73,84.29 39.37,84.92 40,84.92 41.27,83.66 53.34,83.66 53.97,83.02 60.96,83.02 61.59,83.66 74.29,83.66 74.92,83.02 88.89,83.02 89.53,83.66 v93.34,83.66 | v93.34,123.66 92.7,123.03 88.26,123.03 85.08,126.2 13.97,126.2 v13.33,125.56
N$61
  Top 0.254: IC7.19 22.86,110.33 21.58,111.59 21.58,116.04 22.86,117.31 SV3.15
N$62
  Top 0.254: IC7.16 22.86,102.7 21.58,103.97 21.58,110.33 20.95,110.96 20.95,116.67 SV3.13
N$63  (via drill 0.61)
  Top 0.254: v18.41,99.53 18.41,116.67 SV3.11
  Bottom 0.254: v18.41,99.53 22.22,99.53 IC7.15
N$64  (via drill 0.61)
  Top 0.254: v18.41,92.55 18.41,96.99 17.14,98.26 13.97,98.26 13.97,100.8 13.33,101.44 13.33,104.61 12.7,105.25 v12.7,108.42 | v15.87,114.14 15.87,116.67 SV3.9
  Bottom 0.254: v18.41,92.55 22.86,92.55 IC7.12 | v12.7,108.42 1.9,108.42 1.27,109.05 1.27,113.5 3.17,113.5 3.8,114.14 v15.87,114.14
N$65
  Top 0.254: IC7.2 15.24,110.33 13.97,111.59 13.97,116.04 14.6,116.67 14.6,117.94 15.87,119.22 SV3.10
N$66
  Top 0.254: IC7.5 16.5,102.7 17.77,103.97 17.77,116.04 17.14,116.67 17.14,117.94 18.41,119.22 SV3.12
N$67
  Top 0.254: IC7.6 17.14,99.53 18.41,98.26 19.68,98.26 19.68,103.97 19.04,104.61 19.04,116.04 19.68,116.67 19.68,117.94 20.95,119.22 SV3.14
N$68  (via drill 0.61)
  Top 0.254: v23.49,114.14 23.49,114.77 24.76,116.04 24.76,117.94 24.12,118.58 24.12,119.85 SV3.16 | v38.73,108.42 38.73,99.53 39.37,98.89 v39.37,83.66 | v18.41,83.02 17.77,83.66 17.77,91.28 17.14,91.91 IC7.9
  Bottom 0.254: v23.49,114.14 24.12,114.14 24.76,113.5 29.84,113.5 34.92,108.42 v38.73,108.42 | v39.37,83.66 19.04,83.66 v18.41,83.02
N$69
  Top 0.254: IC10.2 40,109.69 38.73,109.69 38.73,117.94 40,119.22 SV4.10
N$70
  Top 0.254: IC10.5 42.54,102.07 43.81,103.34 43.81,117.94 42.54,119.22 SV4.12
N$71  (via drill 0.61)
  Top 0.254: v33.65,98.26 v33.65,121.12
  Bottom 0.254: v33.65,121.12 44.45,121.12 45.08,120.48 SV4.14 | v33.65,98.26 38.1,98.26 39.37,99.53 40,99.53 IC10.6
N$72  (via drill 0.61)
  Top 0.254: v44.45,91.91 44.45,98.89 45.08,99.53 45.08,100.16 44.45,100.8 44.45,114.77 46.35,116.67 46.35,117.94 46.98,118.58 47.62,118.58 47.62,119.22 SV4.16
  Bottom 0.254: v44.45,91.91 42.54,91.91 IC10.9
N$73  (via drill 0.61)
  Top 0.254: v45.72,109.69 45.72,114.77 46.98,116.04 46.98,117.31 SV4.15
  Bottom 0.254: v45.72,109.69 47.62,109.69 IC10.19
N$74
  Top 0.254: IC10.16 48.26,102.7 46.98,103.97 46.98,110.33 46.35,110.96 46.35,114.14 48.89,116.67 48.89,120.48 48.26,121.12 46.35,121.12 46.35,119.22 45.08,117.94 SV4.13
N$75  (via drill 0.61)
  Top 0.254: v50.16,117.31 49.53,116.67 49.53,115.41 46.98,112.86 46.98,111.59 47.62,110.96 50.8,110.96 50.8,100.16 50.16,99.53 IC10.15
  Bottom 0.254: v50.16,117.31 48.89,116.04 43.18,116.04 42.54,116.67 SV4.11
N$76  (via drill 0.61)
  Top 0.254: v50.16,121.12 50.16,118.58 51.43,117.31 51.43,99.53 50.8,98.89 50.8,92.55 50.16,91.91 IC10.12
  Bottom 0.254: v50.16,121.12 46.98,121.12 46.35,120.48 46.35,119.22 45.72,118.58 41.27,118.58 40.64,117.94 40,117.94 SV4.9
N$77
  Top 0.254: IC16.3 66.03,32.85 64.77,31.58 64.77,15.08 66.67,13.17 66.67,11.27 SV5.10
N$78
  Top 0.254: IC16.4 67.3,30.31 68.57,29.04 68.57,18.25 69.84,16.98 69.84,10.63 SV5.12
N$79  (via drill 0.61)
  Top 0.254: v70.48,23.33 70.48,20.15 71.75,18.88 71.75,11.27 SV5.14
  Bottom 0.254: v70.48,23.33 67.94,23.33 IC16.7
N$80  (via drill 0.61)
  Top 0.254: v71.75,20.15 72.38,19.52 72.38,14.44 74.29,12.54 74.29,11.27 SV5.16
  Bottom 0.254: v71.75,20.15 67.3,20.15 IC16.8
N$81  (via drill 0.61)
  Top 0.254: v57.15,86.19 v57.15,91.91 | v21.58,86.19 21.58,100.16 22.22,100.8 25.39,100.8 25.39,114.14 v24.76,114.77
  Bottom 0.254: v57.15,91.91 60.32,91.91 IC11.12 | v57.15,86.19 43.81,86.19 43.18,86.83 31.11,86.83 30.47,86.19 v21.58,86.19 | v24.76,114.77 25.39,114.14 41.27,114.14 42.54,115.41 49.53,115.41 51.43,117.31 55.88,117.31 SV6.1
N$82
  Top 0.254: IC11.15 60.32,99.53 57.78,99.53 57.78,115.41 59.05,116.67 SV6.3
N$83
  Top 0.254: IC11.16 60.96,102.7 59.69,103.97 59.69,114.77 61.59,116.67 SV6.5
N$84
  Top 0.254: IC11.19 62.23,110.33 64.13,112.23 64.13,116.67 SV6.7
N$85  (via drill 0.61)
  Top 0.254: v85.08,77.94 85.08,91.28 85.72,91.91 IC13.12 | v93.97,77.94 95.24,79.21 95.24,112.86 94.61,113.5 v94.61,114.14 | v81.91,115.41 81.91,116.67 SV7.1
  Bottom 0.254: v85.08,77.94 85.72,78.58 93.34,78.58 v93.97,77.94 | v94.61,114.14 93.97,114.77 88.26,114.77 87.62,115.41 v81.91,115.41
N$86  (via drill 0.61)
  Top 0.254: v83.81,100.16 84.45,100.8 84.45,116.67 SV7.3
  Bottom 0.254: v83.81,100.16 86.35,100.16 IC13.15
N$87  (via drill 0.61)
  Top 0.254: v109.21,105.88 109.85,106.52 109.85,122.39 109.21,123.03 v109.21,124.3 | v88.26,124.3 88.26,118.58 87.62,117.94 87.62,117.31 SV7.5
  Bottom 0.254: v109.21,105.88 102.86,105.88 102.86,103.97 103.5,103.34 100.96,100.8 89.53,100.8 88.89,101.44 87.62,101.44 IC13.16 | v109.21,124.3 109.21,126.2 90.16,126.2 v88.26,124.3
N$88
  Top 0.254: IC13.19 87.62,110.33 89.53,112.23 89.53,116.67 SV7.7
N$89  (via drill 0.61)
  Top 0.254: v55.24,122.39 55.24,116.67 55.88,116.04 55.88,102.7 55.24,102.07 IC11.5 | v59.05,122.39 59.05,120.48 SV6.4
  Bottom 0.254: v55.24,122.39 v59.05,122.39
N$90  (via drill 0.61)
  Top 0.254: v43.81,99.53 42.54,100.8 39.37,100.8 39.37,102.7 40,103.34 42.54,103.34 43.18,103.97 43.18,110.33 42.54,110.96 39.37,110.96 39.37,114.77 41.27,116.67 v41.27,123.66 | v61.59,123.66 61.59,120.48 SV6.6
  Bottom 0.254: v43.81,99.53 44.45,99.53 45.72,98.26 50.8,98.26 51.43,98.89 53.34,98.89 IC11.6 | v41.27,123.66 v61.59,123.66
N$91  (via drill 0.61)
  Top 0.254: v58.41,85.56 58.41,84.92 57.15,84.92 55.88,86.19 55.88,91.28 55.24,91.91 IC11.9 | v73.66,85.56 73.66,86.19 76.19,88.73 v76.19,90.64 | v112.39,90.64 112.39,92.55 111.75,93.18 111.75,114.77 113.02,116.04 113.02,119.85 111.75,121.12 111.75,123.03 108.58,126.2 64.13,126.2 64.13,120.48 SV6.8
  Bottom 0.254: v58.41,85.56 60.96,85.56 61.59,84.92 73.02,84.92 v73.66,85.56 | v76.19,90.64 v112.39,90.64
N$92  (via drill 0.61)
  Top 0.254: v67.94,122.39 67.94,117.94 67.3,117.31 SV6.9 | v76.19,110.96 v76.19,121.12 | v69.84,110.33 69.84,107.15 71.75,105.25 71.75,102.07 72.38,101.44 72.38,96.36 73.02,95.72 76.19,95.72 76.19,92.55 75.56,91.91 IC12.12
  Bottom 0.254: v67.94,122.39 68.57,121.75 75.56,121.75 v76.19,121.12 | v76.19,110.96 71.11,110.96 70.48,110.33 v69.84,110.33
N$93  (via drill 0.61)
  Top 0.254: v82.55,114.14 82.55,109.69 83.18,109.05 83.18,107.15 81.91,105.88 81.91,100.16 81.27,99.53 81.27,97.62 81.91,96.99 v81.91,87.47 | v69.84,87.47 v69.84,99.53
  Bottom 0.254: v82.55,114.14 71.75,114.14 69.21,116.67 SV6.11 | v69.84,87.47 v81.91,87.47 | v69.84,99.53 73.02,99.53 IC12.15
N$94  (via drill 0.61)
  Top 0.254: v40,56.35 40.64,56.35 40.64,66.51 39.37,67.78 39.37,69.69 38.73,70.32 v38.73,72.86
  Bottom 0.254: v40,56.35 40.64,56.35 41.91,55.08 45.08,55.08 46.98,53.17 51.43,53.17 52.07,53.81 80.64,53.81 IC24.12 | v38.73,72.86 45.72,72.86 46.98,71.59 47.62,71.59 IC26.4
N$95
  Top 0.254: IC12.16 73.66,102.7 72.38,103.97 72.38,110.33 71.75,110.96 71.75,116.67 SV6.13
N$96
  Top 0.254: IC12.19 73.66,110.33 72.38,111.59 72.38,114.77 74.29,116.67 SV6.15
N$97
  Top 0.254: IC12.2 66.03,110.33 64.77,111.59 64.77,116.04 65.4,116.67 65.4,117.94 66.67,119.22 SV6.10
N$98  (via drill 0.61)
  Top 0.254: v67.94,116.04 68.57,115.41 68.57,102.7 67.94,102.07 IC12.5
  Bottom 0.254: v67.94,116.04 67.94,117.94 69.21,119.22 SV6.12
N$99  (via drill 0.61)
  Top 0.254: v77.46,118.58 77.46,110.96 76.19,109.69 v76.19,98.26
  Bottom 0.254: v77.46,118.58 72.38,118.58 71.75,119.22 SV6.14 | v76.19,98.26 69.21,98.26 68.57,98.89 67.3,98.89 IC12.6
N$100  (via drill 0.61)
  Top 0.254: v68.57,88.1 68.57,91.28 67.94,91.91 IC12.9 | v83.18,88.73 82.55,89.37 82.55,105.25 83.81,106.52 83.81,116.04 83.18,116.67 v83.18,123.66 | v74.29,123.66 74.29,120.48 SV6.16
  Bottom 0.254: v68.57,88.1 69.21,88.73 72.38,88.73 73.02,88.1 81.27,88.1 81.91,88.73 v83.18,88.73 | v83.18,123.66 v74.29,123.66
N$101
  Top 0.254: IC15.3 55.24,33.49 55.24,34.12 59.05,34.12 59.05,23.33 56.51,20.79 56.51,11.27 SV5.2
N$102  (via drill 0.61)
  Top 0.254: v52.07,10 52.07,11.27 51.43,11.9 51.43,29.68 52.7,30.95 IC15.4
  Bottom 0.254: v52.07,10 55.24,10 55.88,9.36 57.15,9.36 57.78,10 59.05,10 SV5.4
N$103  (via drill 0.61)
  Top 0.254: v85.08,9.36 84.45,10 84.45,31.58 v85.08,32.22 | v57.78,32.22 56.51,33.49 55.88,33.49 55.88,32.85 55.24,32.22 55.88,31.58 55.88,23.96 55.24,23.33 IC15.7
  Bottom 0.254: v85.08,9.36 62.23,9.36 61.59,10 SV5.6 | v85.08,32.22 v57.78,32.22
N$104  (via drill 0.61)
  Top 0.254: v55.24,11.9 55.88,12.54 55.88,20.15 55.24,20.79 IC15.8
  Bottom 0.254: v55.24,11.9 63.5,11.9 64.13,11.27 SV5.8
N$105  (via drill 0.61)
  Top 0.254: v68.57,16.98 68.57,11.9 67.94,11.27 67.94,9.36 67.3,8.73 67.3,8.09 SV5.9
  Bottom 0.254: v68.57,16.98 75.56,16.98 76.19,17.61 76.19,18.88 74.92,20.15 IC16.13
N$106
  Top 0.254: IC16.14 73.02,23.33 71.75,23.33 70.48,24.6 69.21,24.6 69.21,18.88 70.48,17.61 70.48,10 69.21,8.73 SV5.11
N$107  (via drill 0.61)
  Top 0.254: v81.27,29.04 81.27,27.14 82.55,25.87 82.55,13.81 v81.27,12.54 | v73.02,12.54 73.02,9.36 72.38,8.73 72.38,8.09 SV5.13
  Bottom 0.254: v81.27,29.04 76.19,29.04 74.92,30.31 IC16.17 | v73.02,12.54 v81.27,12.54
N$108
  Top 0.254: IC16.18 75.56,33.49 76.83,32.22 80.64,32.22 80.64,30.95 83.18,28.41 83.18,12.54 76.19,5.55 74.29,5.55 74.29,7.46 SV5.15
N$109  (via drill 0.61)
  Top 0.254: v57.78,20.79 57.78,9.36 57.15,8.73 57.15,8.09 SV5.1
  Bottom 0.254: v57.78,20.79 60.32,20.79 IC15.13
N$110
  Top 0.254: IC15.14 62.23,22.7 63.5,21.42 63.5,15.08 62.86,14.44 62.86,7.46 62.23,6.82 59.05,6.82 59.05,7.46 SV5.3
N$111
  Top 0.254: IC15.17 60.96,30.31 59.69,29.04 59.69,11.9 60.32,11.27 60.32,10 61.59,8.73 SV5.5
N$112  (via drill 0.61)
  Top 0.254: v65.4,11.9 65.4,8.73 64.77,8.09 SV5.7 | v87.62,22.06 87.62,23.96 86.99,24.6 86.99,44.28 87.62,44.92 87.62,45.55 86.99,46.19 83.81,46.19 83.81,45.55 83.18,44.92 79.37,44.92 78.1,46.19 78.1,50 v78.73,50.63 | v62.86,50 62.86,49.37 63.5,48.73 63.5,34.12 62.86,33.49 IC15.18
  Bottom 0.254: v65.4,11.9 66.03,12.54 68.57,12.54 69.84,13.81 78.73,13.81 84.45,19.52 84.45,22.06 v87.62,22.06 | v78.73,50.63 77.46,49.37 63.5,49.37 v62.86,50
N$113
